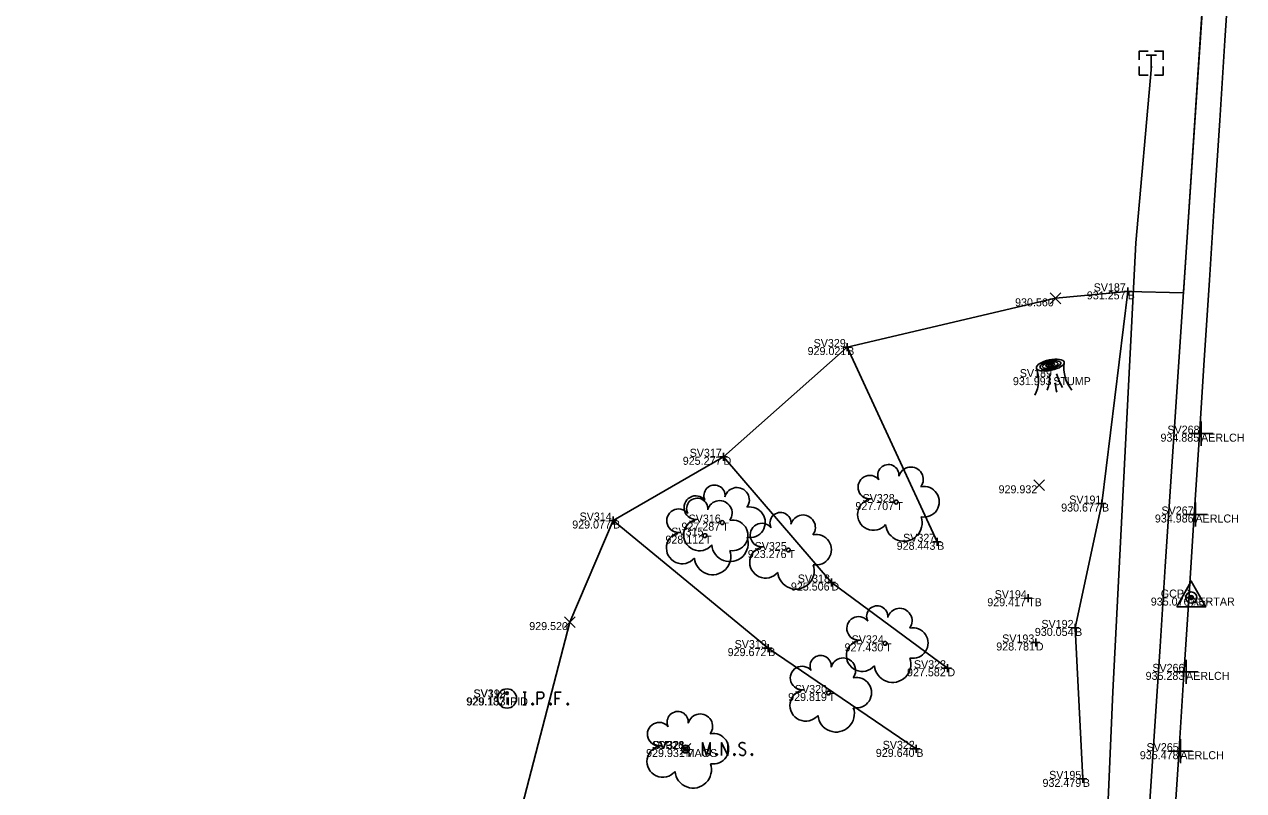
# Model space of a CAD drawing. Extents: x 1988835 to 1989144, y 657973 to 659339.
# Drawn here: x 1988840 to 1988992.3, y 658737.4 to 658833.1 of the extents above; entities that cross this region are included whole.
import ezdxf

# ---------------------------------------------------------------- set-up
doc = ezdxf.new("R2010")
doc.units = 0
for name, color, linetype in [('DR_X_Ditch', 7, 'Continuous'), ('DT_X_Terrain_Boundary', 7, 'Continuous'), ('PV_X_EOP', 7, 'Continuous'), ('PV_X_Shoulder_Aggregate', 7, 'Continuous'), ('SV_P_Control_Cells_Set', 7, 'Continuous'), ('SV_X_Break_Lines', 7, 'Continuous'), ('SV_X_LiDAR_Check_Spots', 7, 'Continuous'), ('SV_X_Mon_Cells_Found', 7, 'Continuous'), ('SV_X_Random_Point', 7, 'Continuous'), ('SV_X_Shot_Marker', 7, 'Continuous'), ('SV_X_Text_Comment', 7, 'Continuous'), ('SV_X_Text_Elevation', 7, 'Continuous'), ('SV_X_Top_of_Bank', 7, 'Continuous'), ('UT_X_Telecom', 7, 'Continuous'), ('UT_X_Telecom_Cells', 7, 'Continuous'), ('VG_X_Cells', 7, 'Continuous')]:
    doc.layers.add(name, color=color, linetype=linetype)

msp = doc.modelspace()

# ---------------------------------------------------------------- linework, layer by layer
at = {"layer": 'DR_X_Ditch'}
for points in [[(1988927.35, 658779.11), (1988940.82, 658763.4), (1988955.32, 658752.69)], [(1988966.36, 658755.91), (1988966.36, 658755.91)]]:
    msp.add_lwpolyline(points, dxfattribs=at)
at = {"layer": 'DT_X_Terrain_Boundary'}
msp.add_lwpolyline([(1988987.83, 658845.23), (1988984.81, 658799.59), (1988977.84, 658799.78), (1988968.83, 658798.91), (1988942.79, 658792.82), (1988927.35, 658779.11), (1988913.54, 658771.15), (1988908.13, 658758.46), (1988901.04, 658731.18), (1988897.02, 658728.69), (1988894.52, 658726.61), (1988891.03, 658722.22), (1988888.81, 658718.86), (1988886.03, 658711.78), (1988888.7, 658704.25), (1988881.58, 658703.53), (1988864.62, 658687.79), (1988839.99, 658661.75), (1988877.26, 658674.92), (1988925.04, 658647.45), (1988929, 658641.52), (1988939.92, 658638.36), (1988953.75, 658630), (1988967.24, 658593.53)], dxfattribs=at)
at = {"layer": 'PV_X_EOP'}
msp.add_lwpolyline([(1988990.64, 658841.1), (1988989.99, 658831.12), (1988989.35, 658821.14), (1988988.7, 658811.16), (1988988.06, 658801.18), (1988987.41, 658791.2), (1988986.77, 658781.22), (1988986.12, 658771.24), (1988985.47, 658761.26), (1988984.83, 658751.29), (1988984.18, 658741.31), (1988983.54, 658731.33), (1988982.89, 658721.35), (1988982.25, 658711.37), (1988981.6, 658701.39), (1988980.96, 658691.41), (1988980.31, 658681.43), (1988979.67, 658671.45), (1988979.02, 658661.47), (1988978.38, 658651.49), (1988977.73, 658641.51), (1988977.08, 658631.54), (1988976.44, 658621.56), (1988975.79, 658611.58)], dxfattribs=at)
at = {"layer": 'PV_X_Shoulder_Aggregate'}
msp.add_lwpolyline([(1988987.17, 658835.25), (1988986.51, 658825.27), (1988985.85, 658815.29), (1988985.19, 658805.31), (1988984.52, 658795.34), (1988983.86, 658785.36), (1988983.2, 658775.38), (1988982.54, 658765.4), (1988981.88, 658755.42), (1988981.22, 658745.44), (1988980.56, 658735.47), (1988979.9, 658725.49), (1988979.24, 658715.51), (1988978.58, 658705.53), (1988977.92, 658695.55), (1988977.25, 658685.58), (1988976.59, 658675.6), (1988975.93, 658665.62), (1988975.27, 658655.64), (1988974.61, 658645.66), (1988973.95, 658635.68), (1988973.29, 658625.71), (1988972.63, 658615.73)], dxfattribs=at)
at = {"layer": 'SV_P_Control_Cells_Set'}
for points in [[(1988924.7, 658741.8), (1988924.7, 658743.4), (1988925.2, 658741.8), (1988925.69, 658743.4), (1988925.69, 658741.8)], [(1988927.07, 658741.8), (1988927.07, 658743.4), (1988927.89, 658741.8), (1988927.89, 658743.4)], [(1988930.04, 658743.29), (1988930.02, 658743.31), (1988929.99, 658743.34), (1988929.89, 658743.37), (1988929.77, 658743.4), (1988929.68, 658743.4), (1988929.65, 658743.4), (1988929.5, 658743.36), (1988929.38, 658743.29), (1988929.31, 658743.19), (1988929.28, 658743.09), (1988929.28, 658743.01), (1988929.31, 658742.91), (1988929.39, 658742.82), (1988930, 658742.44), (1988930.05, 658742.39), (1988930.08, 658742.34), (1988930.1, 658742.27), (1988930.1, 658742.19), (1988930.09, 658742.12), (1988930.08, 658742.06), (1988930.05, 658742), (1988930.03, 658741.95), (1988930.01, 658741.91), (1988929.98, 658741.88), (1988929.94, 658741.85), (1988929.9, 658741.83), (1988929.87, 658741.81), (1988929.77, 658741.8), (1988929.61, 658741.8), (1988929.51, 658741.83), (1988929.37, 658741.91), (1988929.28, 658741.99)], [(1988926.46, 658742.01), (1988926.52, 658742.01), (1988926.55, 658741.99), (1988926.58, 658741.94), (1988926.58, 658741.88), (1988926.55, 658741.83), (1988926.52, 658741.8), (1988926.46, 658741.8), (1988926.43, 658741.83), (1988926.4, 658741.88), (1988926.4, 658741.94), (1988926.43, 658741.99), (1988926.46, 658742.01)], [(1988928.68, 658742.01), (1988928.73, 658742.01), (1988928.77, 658741.99), (1988928.8, 658741.94), (1988928.8, 658741.88), (1988928.77, 658741.83), (1988928.73, 658741.8), (1988928.68, 658741.8), (1988928.64, 658741.83), (1988928.61, 658741.88), (1988928.61, 658741.94), (1988928.64, 658741.99), (1988928.68, 658742.01)], [(1988930.86, 658742.01), (1988930.91, 658742.01), (1988930.95, 658741.99), (1988930.98, 658741.94), (1988930.98, 658741.88), (1988930.95, 658741.83), (1988930.91, 658741.8), (1988930.86, 658741.8), (1988930.83, 658741.83), (1988930.79, 658741.88), (1988930.79, 658741.94), (1988930.83, 658741.99), (1988930.86, 658742.01)]]:
    msp.add_lwpolyline(points, dxfattribs=at)
msp.add_circle((1988922.61, 658742.6), 0.497, dxfattribs=at)
at = {"layer": 'SV_X_Break_Lines'}
for points in [[(1988977.84, 658799.78), (1988974.63, 658773.27), (1988971.27, 658757.73), (1988972.24, 658738.87)], [(1988954.03, 658768.49), (1988942.79, 658792.82)], [(1988913.54, 658771.15), (1988932.92, 658755.21), (1988951.43, 658742.62)], [(1988972.24, 658738.87), (1988972.24, 658738.87)]]:
    msp.add_lwpolyline(points, dxfattribs=at)
at = {"layer": 'SV_X_LiDAR_Check_Spots'}
for p, q in [((1988987.01, 658783.5), (1988987.01, 658780.5)), ((1988985.51, 658782), (1988988.51, 658782)), ((1988987.01, 658782), (1988987.01, 658782)), ((1988986.31, 658773.4), (1988986.31, 658770.4)), ((1988984.81, 658771.9), (1988987.81, 658771.9)), ((1988986.31, 658771.9), (1988986.31, 658771.9)), ((1988985.13, 658753.74), (1988985.13, 658750.74)), ((1988983.63, 658752.24), (1988986.63, 658752.24)), ((1988985.13, 658752.24), (1988985.13, 658752.24)), ((1988984.42, 658743.83), (1988984.42, 658740.83)), ((1988982.92, 658742.33), (1988985.92, 658742.33)), ((1988984.42, 658742.33), (1988984.42, 658742.33))]:
    msp.add_line(p, q, dxfattribs=at)
at = {"layer": 'SV_X_Mon_Cells_Found'}
msp.add_line((1988900.29, 658749.03), (1988900.29, 658748.15), dxfattribs=at)
for points in [[(1988902.32, 658749.71), (1988902.67, 658749.71)], [(1988902.5, 658748.11), (1988902.5, 658749.71)], [(1988904.06, 658748.11), (1988904.06, 658749.71), (1988904.59, 658749.71), (1988904.65, 658749.7), (1988904.72, 658749.68), (1988904.76, 658749.65), (1988904.79, 658749.63), (1988904.83, 658749.56), (1988904.87, 658749.5), (1988904.89, 658749.4), (1988904.89, 658749.25), (1988904.88, 658749.2), (1988904.85, 658749.12), (1988904.81, 658749.03), (1988904.77, 658749), (1988904.73, 658748.97), (1988904.68, 658748.95), (1988904.59, 658748.93), (1988904.06, 658748.93)], [(1988907.07, 658749.71), (1988906.31, 658749.71), (1988906.31, 658748.11)], [(1988906.31, 658748.93), (1988906.85, 658748.93)], [(1988902.32, 658748.11), (1988902.67, 658748.11)], [(1988903.45, 658748.33), (1988903.51, 658748.33), (1988903.54, 658748.3), (1988903.58, 658748.25), (1988903.58, 658748.19), (1988903.54, 658748.14), (1988903.51, 658748.11), (1988903.45, 658748.11), (1988903.42, 658748.14), (1988903.39, 658748.19), (1988903.39, 658748.25), (1988903.42, 658748.3), (1988903.45, 658748.33)], [(1988905.7, 658748.33), (1988905.76, 658748.33), (1988905.79, 658748.3), (1988905.82, 658748.25), (1988905.82, 658748.19), (1988905.79, 658748.14), (1988905.76, 658748.11), (1988905.7, 658748.11), (1988905.67, 658748.14), (1988905.64, 658748.19), (1988905.64, 658748.25), (1988905.67, 658748.3), (1988905.7, 658748.33)], [(1988907.85, 658748.33), (1988907.91, 658748.33), (1988907.94, 658748.3), (1988907.97, 658748.25), (1988907.97, 658748.19), (1988907.94, 658748.14), (1988907.91, 658748.11), (1988907.85, 658748.11), (1988907.82, 658748.14), (1988907.79, 658748.19), (1988907.79, 658748.25), (1988907.82, 658748.3), (1988907.85, 658748.33)]]:
    msp.add_lwpolyline(points, dxfattribs=at)
for centre, radius in [((1988900.29, 658748.91), 1.2), ((1988900.29, 658749.57), 0.16)]:
    msp.add_circle(centre, radius, dxfattribs=at)
at = {"layer": 'SV_X_Random_Point'}
for p, q in [((1988968.16, 658798.24), (1988969.49, 658799.58)), ((1988968.16, 658799.58), (1988969.49, 658798.24)), ((1988966.1, 658774.89), (1988967.43, 658776.22)), ((1988966.1, 658776.22), (1988967.43, 658774.89)), ((1988907.46, 658757.79), (1988908.79, 658759.12)), ((1988907.46, 658759.12), (1988908.79, 658757.79)), ((1988921.94, 658741.93), (1988923.27, 658743.27)), ((1988921.94, 658743.27), (1988923.27, 658741.93)), ((1988921.94, 658741.93), (1988923.27, 658743.27)), ((1988921.94, 658743.27), (1988923.27, 658741.93)), ((1988921.94, 658741.93), (1988923.27, 658743.27)), ((1988921.94, 658743.27), (1988923.27, 658741.93))]:
    msp.add_line(p, q, dxfattribs=at)
at = {"layer": 'SV_X_Shot_Marker'}
for p, q in [((1988977.34, 658799.78), (1988978.34, 658799.78)), ((1988977.84, 658800.28), (1988977.84, 658799.28)), ((1988977.84, 658799.78), (1988977.84, 658799.78)), ((1988942.79, 658793.32), (1988942.79, 658792.32)), ((1988942.29, 658792.82), (1988943.29, 658792.82)), ((1988942.79, 658792.82), (1988942.79, 658792.82)), ((1988927.35, 658779.61), (1988927.35, 658778.61)), ((1988926.85, 658779.11), (1988927.85, 658779.11)), ((1988927.35, 658779.11), (1988927.35, 658779.11)), ((1988974.13, 658773.27), (1988975.13, 658773.27)), ((1988974.63, 658773.77), (1988974.63, 658772.77)), ((1988974.63, 658773.27), (1988974.63, 658773.27)), ((1988913.04, 658771.15), (1988914.04, 658771.15)), ((1988913.54, 658771.65), (1988913.54, 658770.65)), ((1988913.54, 658771.15), (1988913.54, 658771.15)), ((1988954.03, 658768.99), (1988954.03, 658767.99)), ((1988953.53, 658768.49), (1988954.53, 658768.49)), ((1988954.03, 658768.49), (1988954.03, 658768.49)), ((1988940.32, 658763.4), (1988941.32, 658763.4)), ((1988940.82, 658763.9), (1988940.82, 658762.9)), ((1988940.82, 658763.4), (1988940.82, 658763.4)), ((1988964.9, 658761.44), (1988965.9, 658761.44)), ((1988965.4, 658761.94), (1988965.4, 658760.94)), ((1988965.4, 658761.44), (1988965.4, 658761.44)), ((1988971.27, 658758.23), (1988971.27, 658757.23)), ((1988970.77, 658757.73), (1988971.77, 658757.73)), ((1988971.27, 658757.73), (1988971.27, 658757.73)), ((1988932.42, 658755.21), (1988933.42, 658755.21)), ((1988932.92, 658755.71), (1988932.92, 658754.71)), ((1988932.92, 658755.21), (1988932.92, 658755.21)), ((1988965.86, 658755.91), (1988966.86, 658755.91)), ((1988966.36, 658756.41), (1988966.36, 658755.41)), ((1988966.36, 658755.91), (1988966.36, 658755.91)), ((1988954.82, 658752.69), (1988955.82, 658752.69)), ((1988955.32, 658753.19), (1988955.32, 658752.19)), ((1988955.32, 658752.69), (1988955.32, 658752.69)), ((1988951.43, 658743.12), (1988951.43, 658742.12)), ((1988950.93, 658742.62), (1988951.93, 658742.62)), ((1988951.43, 658742.62), (1988951.43, 658742.62)), ((1988971.74, 658738.87), (1988972.74, 658738.87)), ((1988972.24, 658739.37), (1988972.24, 658738.37)), ((1988972.24, 658738.87), (1988972.24, 658738.87))]:
    msp.add_line(p, q, dxfattribs=at)
at = {"layer": 'SV_X_Text_Elevation'}
msp.add_line((1988985.79, 658761.52), (1988985.79, 658761.52), dxfattribs=at)
msp.add_lwpolyline([(1988983.99, 658760.36), (1988987.59, 658760.36), (1988985.79, 658763.58)], close=True, dxfattribs=at)
for radius in [0.7, 0.16]:
    msp.add_circle((1988985.79, 658761.52), radius, dxfattribs=at)
at = {"layer": 'SV_X_Top_of_Bank'}
msp.add_lwpolyline([(1988965.4, 658761.44), (1988965.4, 658761.44)], dxfattribs=at)
at = {"layer": 'UT_X_Telecom'}
msp.add_line((1988985.79, 658761.52), (1988985.79, 658761.52), dxfattribs=at)
msp.add_lwpolyline([(1988967.08, 658620.12), (1988972.73, 658688.59), (1988973.99, 658703.44), (1988976, 658749.74), (1988978.85, 658805.85), (1988980.81, 658827.93)], dxfattribs=at)
msp.add_circle((1988985.79, 658761.52), 0.25, dxfattribs=at)
at = {"layer": 'UT_X_Telecom_Cells'}
for p, q in [((1988980.14, 658829.29), (1988981.43, 658829.29)), ((1988980.78, 658827.29), (1988980.78, 658829.29)), ((1988980.78, 658828.29), (1988980.78, 658828.29))]:
    msp.add_line(p, q, dxfattribs=at)
for points in [[(1988980.39, 658829.79), (1988979.28, 658829.79), (1988979.28, 658828.69)], [(1988982.28, 658828.69), (1988982.28, 658829.79), (1988981.18, 658829.79)], [(1988979.28, 658827.89), (1988979.28, 658826.79), (1988980.39, 658826.79)], [(1988981.18, 658826.79), (1988982.28, 658826.79), (1988982.28, 658827.89)]]:
    msp.add_lwpolyline(points, dxfattribs=at)
at = {"layer": 'VG_X_Cells'}
msp.add_line((1988968.55, 658789.06), (1988968.55, 658789.06), dxfattribs=at)
for centre in [(1988948.93, 658773.45), (1988927.19, 658770.89), (1988925.03, 658769.26), (1988935.45, 658767.46), (1988947.53, 658755.8), (1988940.47, 658749.6), (1988922.61, 658742.6), (1988922.61, 658742.6)]:
    msp.add_circle(centre, 0.24, dxfattribs=at)
for centre, radius, start, end in [((1988962.72, 658788.71), 4, 331.5338, 20.9269), ((1988974.16, 658790.2), 4.29, 171.4106, 219.9194), ((1988963.03, 658789.09), 5.05, 340.7938, 3.5481), ((1988975.06, 658791.12), 6.32, 194.9653, 212.1216), ((1988972.46, 658788.26), 3.64, 178.7926, 197.1224), ((1988947.94, 658776.82), 1.32, 354.0047, 205.9741), ((1988950.75, 658776.28), 1.55, 323.83, 165.0376), ((1988945.62, 658775.31), 1.47, 39.0625, 279.5412), ((1988926.21, 658774.26), 1.32, 354.0047, 205.9741), ((1988929.02, 658773.72), 1.55, 323.83, 165.0376), ((1988952.39, 658773.49), 1.91, 259.1453, 101.4596), ((1988923.88, 658772.76), 1.47, 39.0625, 279.5412), ((1988924.05, 658772.62), 1.32, 354.0047, 205.9741), ((1988926.86, 658772.09), 1.55, 323.83, 165.0376), ((1988946.07, 658771.9), 1.97, 96.1722, 320.5737), ((1988921.72, 658771.12), 1.47, 39.0625, 279.5412), ((1988930.65, 658770.93), 1.91, 259.1453, 101.4596), ((1988934.46, 658770.83), 1.32, 354.0047, 205.9741), ((1988937.27, 658770.29), 1.55, 323.83, 165.0376), ((1988924.34, 658769.34), 1.97, 96.1722, 320.5737), ((1988928.49, 658769.29), 1.91, 259.1453, 101.4596), ((1988932.14, 658769.33), 1.47, 39.0625, 279.5412), ((1988949.87, 658770.84), 2.28, 184.9476, 19.4572), ((1988922.18, 658767.71), 1.97, 96.1722, 320.5737), ((1988928.14, 658768.29), 2.28, 184.9476, 19.4572), ((1988938.91, 658767.5), 1.91, 259.1453, 101.4596), ((1988925.98, 658766.65), 2.28, 184.9476, 19.4572), ((1988932.59, 658765.92), 1.97, 96.1722, 320.5737), ((1988936.39, 658764.86), 2.28, 184.9476, 19.4572), ((1988946.54, 658759.17), 1.32, 354.0047, 205.9741), ((1988949.35, 658758.63), 1.55, 323.83, 165.0376), ((1988944.22, 658757.67), 1.47, 39.0625, 279.5412), ((1988950.99, 658755.84), 1.91, 259.1453, 101.4596), ((1988944.67, 658754.26), 1.97, 96.1722, 320.5737), ((1988939.48, 658752.97), 1.32, 354.0047, 205.9741), ((1988942.29, 658752.43), 1.55, 323.83, 165.0376), ((1988948.47, 658753.2), 2.28, 184.9476, 19.4572), ((1988937.16, 658751.47), 1.47, 39.0625, 279.5412), ((1988943.93, 658749.64), 1.91, 259.1453, 101.4596), ((1988937.61, 658748.05), 1.97, 96.1722, 320.5737), ((1988941.41, 658747), 2.28, 184.9476, 19.4572), ((1988919.3, 658744.46), 1.47, 39.0625, 279.5412), ((1988919.3, 658744.46), 1.47, 39.0625, 279.5412), ((1988921.62, 658745.97), 1.32, 354.0047, 205.9741), ((1988921.62, 658745.97), 1.32, 354.0047, 205.9741), ((1988924.43, 658745.43), 1.55, 323.83, 165.0376), ((1988924.43, 658745.43), 1.55, 323.83, 165.0376), ((1988926.07, 658742.64), 1.91, 259.1453, 101.4596), ((1988926.07, 658742.64), 1.91, 259.1453, 101.4596), ((1988919.75, 658741.05), 1.97, 96.1722, 320.5737), ((1988919.75, 658741.05), 1.97, 96.1722, 320.5737), ((1988923.55, 658740), 2.28, 184.9476, 19.4572), ((1988923.55, 658740), 2.28, 184.9476, 19.4572)]:
    msp.add_arc(centre, radius, start, end, dxfattribs=at)
for major_axis in [(1.74, 0.37), (1.3, 0.28), (0.976, 0.211), (0.549, 0.119), (0.309, 0.067)]:
    msp.add_ellipse((1988968.18, 658790.57), major_axis=major_axis, ratio=0.36865, dxfattribs=at)

# ---------------------------------------------------------------- texts
at = {"layer": 'SV_X_Text_Comment'}
for s, p in [('SV187', (1988973.59, 658799.78)), ('SV329', (1988938.6, 658792.82)), ('SV189', (1988964.36, 658789.06)), ('SV268', (1988982.8, 658782)), ('SV317', (1988923.11, 658779.11)), ('SV328', (1988944.72, 658773.45)), ('SV191', (1988970.54, 658773.27)), ('SV314', (1988909.36, 658771.15)), ('SV316', (1988922.98, 658770.89)), ('SV267', (1988982.06, 658771.9)), ('SV315', (1988920.82, 658769.26)), ('SV327', (1988949.78, 658768.49)), ('SV325', (1988931.23, 658767.46)), ('SV318', (1988936.62, 658763.4)), ('SV194', (1988961.22, 658761.44)), ('GCP3', (1988981.98, 658761.52)), ('SV192', (1988967.06, 658757.73)), ('SV324', (1988943.35, 658755.8)), ('SV193', (1988962.16, 658755.91)), ('SV319', (1988928.73, 658755.21)), ('SV323', (1988951.13, 658752.69)), ('SV266', (1988980.92, 658752.24)), ('SV320', (1988936.26, 658749.6)), ('SV312', (1988896.09, 658749.05)), ('SV199', (1988896.12, 658749.04)), ('SV326', (1988918.4, 658742.6)), ('SV321', (1988918.52, 658742.6)), ('CP13', (1988919.11, 658742.6)), ('SV322', (1988947.23, 658742.62)), ('SV265', (1988980.2, 658742.33)), ('SV195', (1988968.03, 658738.87))]:
    msp.add_text(s, height=1, dxfattribs=at).set_placement(p)
at = {"layer": 'UT_X_Telecom'}
for s, height, p in [('B', 1, (1988977.84, 658798.78)), ('B', 1, (1988942.79, 658791.82)), ('STUMP', 1, (1988968.55, 658788.06)), ('AERLCH', 1, (1988987.01, 658781)), ('D', 1, (1988927.35, 658778.11)), ('T', 1, (1988948.93, 658772.45)), ('B', 1, (1988974.63, 658772.27)), ('AERLCH', 1, (1988986.31, 658770.9)), ('B', 1, (1988913.54, 658770.15)), ('T', 1, (1988927.19, 658769.89)), ('T', 1, (1988925.03, 658768.26)), ('T', 1, (1988935.45, 658766.46)), ('B', 1, (1988954.03, 658767.49)), ('D', 1, (1988940.82, 658762.4)), ('TB', 1, (1988965.4, 658760.44)), ('AERTAR', 1, (1988985.79, 658760.52)), ('Name: GCP3', 0.3, (1988985.79, 658760.82)), ('Index: 2', 0.3, (1988985.79, 658761.22)), ('ΔZ: 0.145', 0.3, (1988985.79, 658760.42)), ('B', 1, (1988971.27, 658756.73)), ('B', 1, (1988932.92, 658754.21)), ('T', 1, (1988947.53, 658754.8)), ('D', 1, (1988966.36, 658754.91)), ('D', 1, (1988955.32, 658751.69)), ('AERLCH', 1, (1988985.13, 658751.24)), ('IPID', 1, (1988900.3, 658748.05)), ('IPID', 1, (1988900.31, 658748.04)), ('T', 1, (1988940.47, 658748.6)), ('T', 1, (1988922.61, 658741.6)), ('T', 1, (1988922.61, 658741.6)), ('MAGS', 1, (1988922.61, 658741.6)), ('B', 1, (1988951.43, 658741.62)), ('AERLCH', 1, (1988984.42, 658741.33)), ('B', 1, (1988972.24, 658737.87))]:
    msp.add_text(s, height=height, dxfattribs=at).set_placement(p)
at = {"layer": 'UT_X_Telecom_Cells'}
for s, p in [('931.257', (1988972.74, 658798.78)), ('930.560', (1988963.77, 658797.91)), ('929.021', (1988937.85, 658791.82)), ('931.993', (1988963.5, 658788.06)), ('934.885', (1988981.94, 658781)), ('925.277', (1988922.25, 658778.11)), ('929.932', (1988961.71, 658774.55)), ('927.707', (1988943.82, 658772.45)), ('930.677', (1988969.53, 658772.27)), ('934.986', (1988981.24, 658770.9)), ('929.077', (1988908.44, 658770.15)), ('927.287', (1988922.09, 658769.89)), ('928.112', (1988920.08, 658768.26)), ('923.276', (1988930.38, 658766.46)), ('928.443', (1988948.98, 658767.49)), ('925.506', (1988935.76, 658762.4)), ('929.417', (1988960.3, 658760.44)), ('935.076', (1988980.73, 658760.52)), ('929.520', (1988903.07, 658757.46)), ('930.054', (1988966.24, 658756.73)), ('929.672', (1988927.86, 658754.21)), ('927.430', (1988942.47, 658754.8)), ('928.781', (1988961.42, 658754.91)), ('927.582', (1988950.27, 658751.69)), ('935.283', (1988980.08, 658751.24)), ('929.187', (1988895.19, 658748.05)), ('929.133', (1988895.26, 658748.04)), ('929.819', (1988935.42, 658748.6)), ('929.931', (1988917.67, 658741.6)), ('929.931', (1988917.67, 658741.6)), ('929.931', (1988917.67, 658741.6)), ('929.931', (1988917.67, 658741.6)), ('929.931', (1988917.67, 658741.6)), ('929.931', (1988917.67, 658741.6)), ('929.640', (1988946.37, 658741.62)), ('935.478', (1988979.36, 658741.33)), ('932.479', (1988967.2, 658737.87))]:
    msp.add_text(s, height=1, dxfattribs=at).set_placement(p)

doc.saveas('drawing.dxf')
